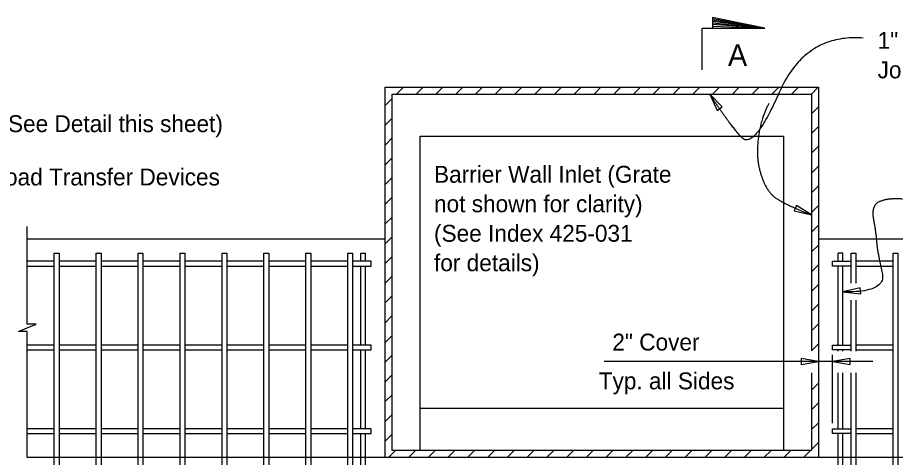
# Model space of a CAD drawing. Extents: x 0.2 to 40.3, y 0.2 to 25.7.
# Drawn here: x 16.33 to 26.79, y 20.45 to 25.7 of the extents above; entities that cross this region are included whole.
import ezdxf

# ---------------------------------------------------------------- set-up
doc = ezdxf.new("R2010")
doc.units = 0
for name, color, linetype in [('Dimension', 7, 'Continuous'), ('Miscellaneous', 7, 'Continuous'), ('Rebar', 7, 'Continuous'), ('TextStructures', 7, 'Continuous'), ('TrafBarrierConc', 7, 'Continuous')]:
    doc.layers.add(name, color=color, linetype=linetype)

msp = doc.modelspace()

# ---------------------------------------------------------------- linework, layer by layer
at = {"layer": 'Dimension'}
for p, q in [((25.237, 25.575), (24.612, 25.685)), ((24.612, 25.672), (25.237, 25.575)), ((25.237, 25.575), (24.612, 25.655)), ((24.612, 25.637), (25.237, 25.575)), ((25.237, 25.575), (24.612, 25.619)), ((24.612, 25.599), (25.237, 25.575)), ((26.042, 20.862), (26.042, 21.677)), ((26.523, 21.596), (23.318, 21.596))]:
    msp.add_line(p, q, dxfattribs=at)
for points in [[(24.487, 25.075), (24.487, 25.575), (25.237, 25.575), (24.612, 25.7), (24.612, 25.575)], [(16.442, 20.451), (16.442, 21.952), (16.339, 21.952), (16.442, 21.997), (16.546, 22.042), (16.442, 22.042), (16.442, 23.205)]]:
    msp.add_lwpolyline(points, dxfattribs=at)
for points in [[(24.578, 24.784), (24.667, 24.593), (24.725, 24.633)], [(25.792, 23.346), (25.613, 23.458), (25.586, 23.393)], [(26.167, 22.426), (26.378, 22.404), (26.373, 22.474)], [(25.876, 21.596), (25.668, 21.632), (25.668, 21.561)], [(26.042, 21.596), (26.251, 21.561), (26.251, 21.632)]]:
    msp.add_lwpolyline(points, close=True, dxfattribs=at)
for points in [[(26.409, 25.455), (25.718, 25.509), (25.102, 24.117), (24.824, 24.415), (24.578, 24.784)], [(25.284, 24.674), (25.192, 24.513), (25.126, 24.035), (25.239, 23.662), (25.42, 23.49), (25.792, 23.346)], [(26.878, 23.534), (26.696, 23.547), (26.5, 23.456), (26.56, 23.132), (26.578, 22.895), (26.692, 22.416), (26.167, 22.426)]]:
    msp.add_open_spline(points, degree=2, dxfattribs=at)
at = {"layer": 'Miscellaneous'}
for p, q in [((20.843, 24.784), (20.926, 24.868)), ((21.079, 24.784), (21.162, 24.868)), ((21.314, 24.784), (21.398, 24.868)), ((21.55, 24.784), (21.633, 24.868)), ((21.785, 24.784), (21.869, 24.868)), ((22.021, 24.784), (22.104, 24.868)), ((22.256, 24.784), (22.34, 24.868)), ((22.492, 24.784), (22.575, 24.868)), ((22.728, 24.784), (22.811, 24.868)), ((22.963, 24.784), (23.046, 24.868)), ((23.199, 24.784), (23.282, 24.868)), ((23.434, 24.784), (23.518, 24.868)), ((23.67, 24.784), (23.753, 24.868)), ((23.905, 24.784), (23.989, 24.868)), ((24.141, 24.784), (24.224, 24.868)), ((24.376, 24.784), (24.46, 24.868)), ((24.612, 24.784), (24.695, 24.868)), ((24.848, 24.784), (24.931, 24.868)), ((25.083, 24.784), (25.166, 24.868)), ((25.319, 24.784), (25.402, 24.868)), ((25.554, 24.784), (25.638, 24.868)), ((25.79, 24.784), (25.873, 24.868)), ((20.709, 24.65), (20.792, 24.734)), ((20.792, 20.534), (20.792, 24.784)), ((20.792, 24.784), (25.792, 24.784)), ((25.792, 24.784), (25.792, 21.723)), ((25.792, 24.552), (25.876, 24.635)), ((20.709, 24.415), (20.792, 24.498)), ((25.792, 24.316), (25.876, 24.399)), ((21.126, 24.284), (25.459, 24.284)), ((21.126, 20.534), (21.126, 24.284)), ((25.459, 24.284), (25.459, 20.534)), ((20.709, 24.179), (20.792, 24.263)), ((25.792, 24.08), (25.876, 24.164)), ((20.709, 23.944), (20.792, 24.027)), ((25.792, 23.845), (25.876, 23.928)), ((20.709, 23.708), (20.792, 23.791)), ((25.792, 23.609), (25.876, 23.693)), ((20.709, 23.473), (20.792, 23.556)), ((25.792, 23.374), (25.876, 23.457)), ((20.709, 23.237), (20.792, 23.32)), ((25.792, 23.138), (25.876, 23.221)), ((20.709, 23.002), (20.792, 23.085)), ((25.792, 22.903), (25.876, 22.986)), ((20.709, 22.766), (20.792, 22.849)), ((25.792, 22.667), (25.876, 22.75)), ((20.709, 22.53), (20.792, 22.614)), ((25.792, 22.432), (25.876, 22.515)), ((20.709, 22.295), (20.792, 22.378)), ((25.792, 22.196), (25.876, 22.279)), ((20.709, 22.059), (20.792, 22.143)), ((25.792, 21.96), (25.876, 22.044)), ((20.709, 21.824), (20.792, 21.907)), ((25.792, 21.725), (25.876, 21.808)), ((20.709, 21.588), (20.792, 21.671)), ((25.792, 21.461), (25.792, 20.534)), ((20.709, 21.353), (20.792, 21.436)), ((25.792, 21.254), (25.876, 21.337)), ((20.709, 21.117), (20.792, 21.2)), ((25.792, 21.018), (25.876, 21.101)), ((20.709, 20.882), (20.792, 20.965)), ((25.459, 21.034), (21.126, 21.034)), ((25.792, 20.783), (25.876, 20.866)), ((20.709, 20.646), (20.792, 20.729)), ((25.792, 20.547), (25.876, 20.63)), ((20.75, 20.451), (20.833, 20.534)), ((25.792, 20.534), (20.792, 20.534)), ((20.985, 20.451), (21.069, 20.534)), ((21.221, 20.451), (21.304, 20.534)), ((21.456, 20.451), (21.54, 20.534)), ((21.692, 20.451), (21.775, 20.534)), ((21.928, 20.451), (22.011, 20.534)), ((22.163, 20.451), (22.246, 20.534)), ((22.399, 20.451), (22.482, 20.534)), ((22.634, 20.451), (22.718, 20.534)), ((22.87, 20.451), (22.953, 20.534)), ((23.105, 20.451), (23.189, 20.534)), ((23.341, 20.451), (23.424, 20.534)), ((23.576, 20.451), (23.66, 20.534)), ((23.812, 20.451), (23.895, 20.534)), ((24.048, 20.451), (24.131, 20.534)), ((24.283, 20.451), (24.366, 20.534)), ((24.519, 20.451), (24.602, 20.534)), ((24.754, 20.451), (24.838, 20.534)), ((24.99, 20.451), (25.073, 20.534)), ((25.225, 20.451), (25.309, 20.534)), ((25.461, 20.451), (25.544, 20.534)), ((25.696, 20.451), (25.78, 20.534))]:
    msp.add_line(p, q, dxfattribs=at)
at = {"layer": 'Rebar'}
for p, q in [((20.417, 22.889), (20.475, 22.889)), ((20.417, 22.792), (20.417, 22.889)), ((20.475, 22.792), (20.475, 22.889)), ((26.167, 22.889), (26.11, 22.889)), ((26.11, 22.792), (26.11, 22.889)), ((26.167, 22.792), (26.167, 22.889)), ((20.417, 21.792), (20.417, 22.735)), ((20.475, 21.792), (20.475, 22.735)), ((20.543, 22.735), (20.543, 22.792)), ((26.042, 22.735), (26.042, 22.792)), ((26.11, 21.792), (26.11, 22.735)), ((26.167, 21.792), (26.167, 22.735)), ((20.543, 21.735), (20.543, 21.792)), ((26.042, 21.735), (26.042, 21.792)), ((20.417, 20.792), (20.417, 21.735)), ((20.475, 20.792), (20.475, 21.735)), ((26.11, 21.718), (26.11, 21.735)), ((26.167, 21.718), (26.167, 21.735)), ((26.11, 20.792), (26.11, 21.462)), ((26.167, 20.792), (26.167, 21.462)), ((20.417, 20.17), (20.417, 20.735)), ((20.475, 20.227), (20.475, 20.735)), ((20.543, 20.735), (20.543, 20.792)), ((26.042, 20.735), (26.042, 20.792)), ((26.11, 20.227), (26.11, 20.735)), ((26.167, 20.17), (26.167, 20.735))]:
    msp.add_line(p, q, dxfattribs=at)
for points in [[(16.764, 22.889), (16.821, 22.889), (16.821, 16.222), (16.764, 16.222)], [(17.264, 22.889), (17.321, 22.889), (17.321, 16.222), (17.264, 16.222)], [(17.764, 22.889), (17.821, 22.889), (17.821, 16.222), (17.764, 16.222)], [(18.264, 22.889), (18.321, 22.889), (18.321, 16.222), (18.264, 16.222)], [(18.764, 22.889), (18.821, 22.889), (18.821, 16.222), (18.764, 16.222)], [(19.264, 22.889), (19.321, 22.889), (19.321, 16.222), (19.264, 16.222)], [(19.764, 22.889), (19.821, 22.889), (19.821, 16.222), (19.764, 16.222)], [(20.264, 22.889), (20.321, 22.889), (20.321, 16.222), (20.264, 16.222)], [(26.764, 22.889), (26.821, 22.889), (26.821, 16.222), (26.764, 16.222)]]:
    msp.add_lwpolyline(points, close=True, dxfattribs=at)
for points in [[(26.264, 22.53), (26.264, 22.889), (26.321, 22.889), (26.321, 22.53)], [(16.764, 22.792), (16.442, 22.792)], [(16.442, 22.735), (16.764, 22.735)], [(17.264, 22.792), (16.821, 22.792)], [(16.821, 22.735), (17.264, 22.735)], [(17.764, 22.792), (17.321, 22.792)], [(17.321, 22.735), (17.764, 22.735)], [(18.264, 22.792), (17.821, 22.792)], [(17.821, 22.735), (18.264, 22.735)], [(18.764, 22.792), (18.321, 22.792)], [(18.321, 22.735), (18.764, 22.735)], [(19.264, 22.792), (18.821, 22.792)], [(18.821, 22.735), (19.264, 22.735)], [(19.764, 22.792), (19.321, 22.792)], [(19.321, 22.735), (19.764, 22.735)], [(20.264, 22.792), (19.821, 22.792)], [(19.821, 22.735), (20.264, 22.735)], [(20.543, 22.792), (20.321, 22.792)], [(20.321, 22.735), (20.543, 22.735)], [(26.042, 22.792), (26.264, 22.792)], [(26.264, 22.735), (26.042, 22.735)], [(26.764, 22.792), (26.321, 22.792)], [(26.321, 22.735), (26.764, 22.735)], [(26.264, 21.718), (26.264, 22.329)], [(26.321, 22.329), (26.321, 21.718)], [(16.764, 21.792), (16.442, 21.792)], [(17.264, 21.792), (16.821, 21.792)], [(17.764, 21.792), (17.321, 21.792)], [(18.264, 21.792), (17.821, 21.792)], [(18.764, 21.792), (18.321, 21.792)], [(19.264, 21.792), (18.821, 21.792)], [(19.764, 21.792), (19.321, 21.792)], [(20.264, 21.792), (19.821, 21.792)], [(20.543, 21.792), (20.321, 21.792)], [(26.042, 21.792), (26.264, 21.792)], [(26.764, 21.792), (26.321, 21.792)], [(16.442, 21.735), (16.764, 21.735)], [(16.821, 21.735), (17.264, 21.735)], [(17.321, 21.735), (17.764, 21.735)], [(17.821, 21.735), (18.264, 21.735)], [(18.321, 21.735), (18.764, 21.735)], [(18.821, 21.735), (19.264, 21.735)], [(19.321, 21.735), (19.764, 21.735)], [(19.821, 21.735), (20.264, 21.735)], [(20.321, 21.735), (20.543, 21.735)], [(26.264, 21.735), (26.042, 21.735)], [(26.321, 21.735), (26.764, 21.735)], [(26.321, 21.462), (26.321, 16.222), (26.264, 16.222), (26.264, 21.462)], [(16.764, 20.792), (16.442, 20.792)], [(16.442, 20.735), (16.764, 20.735)], [(17.264, 20.792), (16.821, 20.792)], [(16.821, 20.735), (17.264, 20.735)], [(17.764, 20.792), (17.321, 20.792)], [(17.321, 20.735), (17.764, 20.735)], [(18.264, 20.792), (17.821, 20.792)], [(17.821, 20.735), (18.264, 20.735)], [(18.764, 20.792), (18.321, 20.792)], [(18.321, 20.735), (18.764, 20.735)], [(19.264, 20.792), (18.821, 20.792)], [(18.821, 20.735), (19.264, 20.735)], [(19.764, 20.792), (19.321, 20.792)], [(19.321, 20.735), (19.764, 20.735)], [(20.264, 20.792), (19.821, 20.792)], [(19.821, 20.735), (20.264, 20.735)], [(20.543, 20.792), (20.321, 20.792)], [(20.321, 20.735), (20.543, 20.735)], [(26.042, 20.792), (26.264, 20.792)], [(26.264, 20.735), (26.042, 20.735)], [(26.764, 20.792), (26.321, 20.792)], [(26.321, 20.735), (26.764, 20.735)]]:
    msp.add_lwpolyline(points, dxfattribs=at)
at = {"layer": 'TrafBarrierConc'}
for p, q in [((20.709, 24.868), (25.876, 24.868)), ((20.709, 20.451), (20.709, 24.868)), ((25.876, 24.868), (25.876, 20.451)), ((20.709, 23.055), (16.442, 23.055)), ((29.4, 23.055), (25.876, 23.055)), ((29.422, 20.451), (16.442, 20.451))]:
    msp.add_line(p, q, dxfattribs=at)

# ---------------------------------------------------------------- texts
at = {"layer": 'Dimension'}
for s, p in [('1" Preformed Expansion ', (26.58, 25.327)), ('Joint Filler (Typ. all Sides)', (26.58, 24.975)), ('Barrier Wall Inlet (Grate ', (21.291, 23.729)), ('not shown for clarity)  ', (21.291, 23.377)), ('(See Index 425-031', (21.291, 23.025)), ('for details)', (21.291, 22.673))]:
    msp.add_text(s, height=0.2016, dxfattribs=at).set_placement(p)
at = {"layer": 'TextStructures'}
for s, height, p in [('A', 0.256, (24.796, 25.124)), ('Expansion Joint (See Detail this sheet)', 0.2016, (14.144, 24.333)), ('1" Ø Dowel Load Transfer Devices ', 0.2016, (14.597, 23.697)), ('2" Cover', 0.2016, (23.417, 21.727)), ('Typ. all Sides', 0.2016, (23.255, 21.264))]:
    msp.add_text(s, height=height, dxfattribs=at).set_placement(p)

doc.saveas('drawing.dxf')
